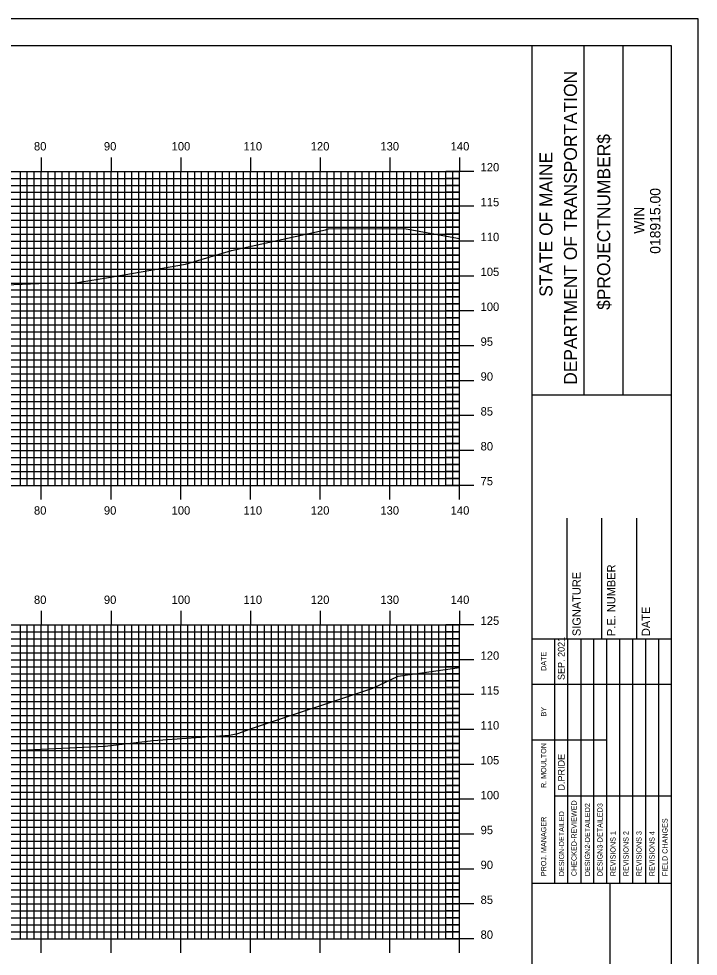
# Model space of a CAD drawing. Extents: x 1755495 to 1755838, y 442591 to 442811.
# Drawn here: x 1755737.3 to 1755834.8, y 442676.2 to 442810.5 of the extents above; entities that cross this region are included whole.
import ezdxf

# ---------------------------------------------------------------- set-up
doc = ezdxf.new("R2010")
doc.units = 0
for name, color, linetype in [('BORDER', 7, 'Continuous'), ('H_V ANNOTATION', 7, 'Continuous'), ('MAJOR', 7, 'Continuous'), ('MINOR', 7, 'Continuous'), ('PLOT BOUNDARY', 7, 'Continuous'), ('S_Roadway_Centerline', 7, 'Continuous')]:
    doc.layers.add(name, color=color, linetype=linetype)

msp = doc.modelspace()

# ---------------------------------------------------------------- linework, layer by layer
at = {"layer": 'BORDER'}
for p, q in [((1755810.94, 442596.67), (1755810.94, 442806.67)), ((1755818.4, 442756.66), (1755818.4, 442806.66)), ((1755823.99, 442756.66), (1755823.99, 442806.66)), ((1755810.95, 442756.65), (1755830.94, 442756.65)), ((1755815.94, 442721.67), (1755815.94, 442738.97)), ((1755820.94, 442721.67), (1755820.94, 442738.97)), ((1755825.94, 442721.67), (1755825.94, 442738.97)), ((1755810.94, 442721.67), (1755830.94, 442721.67)), ((1755810.94, 442686.67), (1755830.94, 442686.67)), ((1755822.13, 442616.67), (1755822.13, 442686.67))]:
    msp.add_line(p, q, dxfattribs=at)
msp.add_lwpolyline([(1755510.94, 442596.67), (1755830.94, 442596.67), (1755830.94, 442806.67), (1755510.94, 442806.67)], close=True, dxfattribs=at)
for points in [[(1755814.17, 442715.17), (1755814.17, 442721.67)], [(1755816.04, 442686.68), (1755816.04, 442721.67)], [(1755817.9, 442721.67), (1755817.9, 442686.68)], [(1755819.77, 442686.68), (1755819.77, 442721.67)], [(1755821.63, 442686.68), (1755821.63, 442721.67)], [(1755823.49, 442686.68), (1755823.49, 442721.67)], [(1755825.36, 442686.68), (1755825.36, 442721.67)], [(1755827.22, 442686.68), (1755827.22, 442721.67)], [(1755829.08, 442686.68), (1755829.08, 442721.67)], [(1755814.18, 442686.68), (1755814.18, 442720.26)], [(1755810.94, 442715.17), (1755830.94, 442715.17)], [(1755810.94, 442707.17), (1755814.18, 442707.17)], [(1755814.17, 442707.17), (1755821.63, 442707.17)], [(1755814.17, 442699.17), (1755830.94, 442699.17)]]:
    msp.add_lwpolyline(points, dxfattribs=at)
at = {"layer": 'MAJOR'}
for p, q in [((1755740.54, 442790.67), (1755740.54, 442788.67)), ((1755750.54, 442790.67), (1755750.54, 442788.67)), ((1755760.54, 442790.67), (1755760.54, 442788.67)), ((1755770.54, 442790.67), (1755770.54, 442788.67)), ((1755780.54, 442790.67), (1755780.54, 442788.67)), ((1755790.54, 442790.67), (1755790.54, 442788.67)), ((1755800.54, 442790.67), (1755800.54, 442788.67)), ((1755520.54, 442788.67), (1755800.54, 442788.67)), ((1755520.54, 442788.67), (1755800.54, 442788.67)), ((1755740.54, 442743.67), (1755740.54, 442788.67)), ((1755750.54, 442743.67), (1755750.54, 442788.67)), ((1755760.54, 442743.67), (1755760.54, 442788.67)), ((1755770.54, 442743.67), (1755770.54, 442788.67)), ((1755780.54, 442743.67), (1755780.54, 442788.67)), ((1755790.54, 442743.67), (1755790.54, 442788.67)), ((1755802.55, 442788.67), (1755798.54, 442788.67)), ((1755800.54, 442743.67), (1755800.54, 442788.67)), ((1755800.54, 442743.67), (1755800.54, 442788.67)), ((1755520.54, 442783.67), (1755800.54, 442783.67)), ((1755802.55, 442783.67), (1755798.54, 442783.67)), ((1755520.54, 442778.67), (1755800.54, 442778.67)), ((1755802.55, 442778.67), (1755798.54, 442778.67)), ((1755520.54, 442773.67), (1755800.54, 442773.67)), ((1755802.55, 442773.67), (1755798.54, 442773.67)), ((1755520.54, 442768.67), (1755800.54, 442768.67)), ((1755802.55, 442768.67), (1755798.54, 442768.67)), ((1755520.54, 442763.67), (1755800.54, 442763.67)), ((1755802.55, 442763.67), (1755798.54, 442763.67)), ((1755520.54, 442758.67), (1755800.54, 442758.67)), ((1755802.55, 442758.67), (1755798.54, 442758.67)), ((1755520.54, 442753.67), (1755800.54, 442753.67)), ((1755802.55, 442753.67), (1755798.54, 442753.67)), ((1755520.54, 442748.67), (1755800.54, 442748.67)), ((1755802.55, 442748.67), (1755798.54, 442748.67)), ((1755520.54, 442743.67), (1755800.54, 442743.67)), ((1755520.54, 442743.67), (1755800.54, 442743.67)), ((1755740.54, 442741.66), (1755740.54, 442743.67)), ((1755750.54, 442741.66), (1755750.54, 442743.67)), ((1755760.54, 442741.66), (1755760.54, 442743.67)), ((1755770.54, 442741.66), (1755770.54, 442743.67)), ((1755780.54, 442741.66), (1755780.54, 442743.67)), ((1755790.54, 442741.66), (1755790.54, 442743.67)), ((1755802.55, 442743.67), (1755798.54, 442743.67)), ((1755800.54, 442741.66), (1755800.54, 442743.67)), ((1755740.54, 442725.67), (1755740.54, 442723.67)), ((1755750.54, 442725.67), (1755750.54, 442723.67)), ((1755760.54, 442725.67), (1755760.54, 442723.67)), ((1755770.54, 442725.67), (1755770.54, 442723.67)), ((1755780.54, 442725.67), (1755780.54, 442723.67)), ((1755790.54, 442725.67), (1755790.54, 442723.67)), ((1755800.54, 442725.67), (1755800.54, 442723.67)), ((1755520.54, 442723.67), (1755800.54, 442723.67)), ((1755520.54, 442723.67), (1755800.54, 442723.67)), ((1755740.54, 442678.67), (1755740.54, 442723.67)), ((1755750.54, 442678.67), (1755750.54, 442723.67)), ((1755760.54, 442678.67), (1755760.54, 442723.67)), ((1755770.54, 442678.67), (1755770.54, 442723.67)), ((1755780.54, 442678.67), (1755780.54, 442723.67)), ((1755790.54, 442678.67), (1755790.54, 442723.67)), ((1755802.55, 442723.67), (1755798.54, 442723.67)), ((1755800.54, 442678.67), (1755800.54, 442723.67)), ((1755800.54, 442678.67), (1755800.54, 442723.67)), ((1755520.54, 442718.67), (1755800.54, 442718.67)), ((1755802.55, 442718.67), (1755798.54, 442718.67)), ((1755520.54, 442713.67), (1755800.54, 442713.67)), ((1755802.55, 442713.67), (1755798.54, 442713.67)), ((1755520.54, 442708.67), (1755800.54, 442708.67)), ((1755802.55, 442708.67), (1755798.54, 442708.67)), ((1755520.54, 442703.67), (1755800.54, 442703.67)), ((1755802.55, 442703.67), (1755798.54, 442703.67)), ((1755520.54, 442698.67), (1755800.54, 442698.67)), ((1755802.55, 442698.67), (1755798.54, 442698.67)), ((1755520.54, 442693.67), (1755800.54, 442693.67)), ((1755802.55, 442693.67), (1755798.54, 442693.67)), ((1755520.54, 442688.67), (1755800.54, 442688.67)), ((1755802.55, 442688.67), (1755798.54, 442688.67)), ((1755520.54, 442683.67), (1755800.54, 442683.67)), ((1755802.55, 442683.67), (1755798.54, 442683.67)), ((1755520.54, 442678.67), (1755800.54, 442678.67)), ((1755520.54, 442678.67), (1755800.54, 442678.67)), ((1755740.54, 442676.66), (1755740.54, 442678.67)), ((1755750.54, 442676.66), (1755750.54, 442678.67)), ((1755760.54, 442676.66), (1755760.54, 442678.67)), ((1755770.54, 442676.66), (1755770.54, 442678.67)), ((1755780.54, 442676.66), (1755780.54, 442678.67)), ((1755790.54, 442676.66), (1755790.54, 442678.67)), ((1755802.55, 442678.67), (1755798.54, 442678.67)), ((1755800.54, 442676.66), (1755800.54, 442678.67))]:
    msp.add_line(p, q, dxfattribs=at)
at = {"layer": 'MINOR'}
for p, q in [((1755737.54, 442743.67), (1755737.54, 442788.67)), ((1755738.54, 442743.67), (1755738.54, 442788.67)), ((1755739.54, 442743.67), (1755739.54, 442788.67)), ((1755741.54, 442743.67), (1755741.54, 442788.67)), ((1755742.54, 442743.67), (1755742.54, 442788.67)), ((1755743.54, 442743.67), (1755743.54, 442788.67)), ((1755744.54, 442743.67), (1755744.54, 442788.67)), ((1755745.54, 442743.67), (1755745.54, 442788.67)), ((1755746.54, 442743.67), (1755746.54, 442788.67)), ((1755747.54, 442743.67), (1755747.54, 442788.67)), ((1755748.54, 442743.67), (1755748.54, 442788.67)), ((1755749.54, 442743.67), (1755749.54, 442788.67)), ((1755751.54, 442743.67), (1755751.54, 442788.67)), ((1755752.54, 442743.67), (1755752.54, 442788.67)), ((1755753.54, 442743.67), (1755753.54, 442788.67)), ((1755754.54, 442743.67), (1755754.54, 442788.67)), ((1755755.54, 442743.67), (1755755.54, 442788.67)), ((1755756.54, 442743.67), (1755756.54, 442788.67)), ((1755757.54, 442743.67), (1755757.54, 442788.67)), ((1755758.54, 442743.67), (1755758.54, 442788.67)), ((1755759.54, 442743.67), (1755759.54, 442788.67)), ((1755761.54, 442743.67), (1755761.54, 442788.67)), ((1755762.54, 442743.67), (1755762.54, 442788.67)), ((1755763.54, 442743.67), (1755763.54, 442788.67)), ((1755764.54, 442743.67), (1755764.54, 442788.67)), ((1755765.54, 442743.67), (1755765.54, 442788.67)), ((1755766.54, 442743.67), (1755766.54, 442788.67)), ((1755767.54, 442743.67), (1755767.54, 442788.67)), ((1755768.54, 442743.67), (1755768.54, 442788.67)), ((1755769.54, 442743.67), (1755769.54, 442788.67)), ((1755771.54, 442743.67), (1755771.54, 442788.67)), ((1755772.54, 442743.67), (1755772.54, 442788.67)), ((1755773.54, 442743.67), (1755773.54, 442788.67)), ((1755774.54, 442743.67), (1755774.54, 442788.67)), ((1755775.54, 442743.67), (1755775.54, 442788.67)), ((1755776.54, 442743.67), (1755776.54, 442788.67)), ((1755777.54, 442743.67), (1755777.54, 442788.67)), ((1755778.54, 442743.67), (1755778.54, 442788.67)), ((1755779.54, 442743.67), (1755779.54, 442788.67)), ((1755781.54, 442743.67), (1755781.54, 442788.67)), ((1755782.54, 442743.67), (1755782.54, 442788.67)), ((1755783.54, 442743.67), (1755783.54, 442788.67)), ((1755784.54, 442743.67), (1755784.54, 442788.67)), ((1755785.54, 442743.67), (1755785.54, 442788.67)), ((1755786.54, 442743.67), (1755786.54, 442788.67)), ((1755787.54, 442743.67), (1755787.54, 442788.67)), ((1755788.54, 442743.67), (1755788.54, 442788.67)), ((1755789.54, 442743.67), (1755789.54, 442788.67)), ((1755791.54, 442743.67), (1755791.54, 442788.67)), ((1755792.54, 442743.67), (1755792.54, 442788.67)), ((1755793.54, 442743.67), (1755793.54, 442788.67)), ((1755794.54, 442743.67), (1755794.54, 442788.67)), ((1755795.54, 442743.67), (1755795.54, 442788.67)), ((1755796.54, 442743.67), (1755796.54, 442788.67)), ((1755797.54, 442743.67), (1755797.54, 442788.67)), ((1755798.54, 442743.67), (1755798.54, 442788.67)), ((1755799.54, 442743.67), (1755799.54, 442788.67)), ((1755520.54, 442787.67), (1755800.54, 442787.67)), ((1755520.54, 442786.67), (1755800.54, 442786.67)), ((1755800.54, 442787.67), (1755798.54, 442787.67)), ((1755800.54, 442786.67), (1755798.54, 442786.67)), ((1755520.54, 442785.67), (1755800.54, 442785.67)), ((1755800.54, 442785.67), (1755798.54, 442785.67)), ((1755520.54, 442784.67), (1755800.54, 442784.67)), ((1755800.54, 442784.67), (1755798.54, 442784.67)), ((1755520.54, 442782.67), (1755800.54, 442782.67)), ((1755800.54, 442782.67), (1755798.54, 442782.67)), ((1755520.54, 442781.67), (1755800.54, 442781.67)), ((1755800.54, 442781.67), (1755798.54, 442781.67)), ((1755520.54, 442780.67), (1755800.54, 442780.67)), ((1755520.54, 442779.67), (1755800.54, 442779.67)), ((1755800.54, 442780.67), (1755798.54, 442780.67)), ((1755800.54, 442779.67), (1755798.54, 442779.67)), ((1755520.54, 442777.67), (1755800.54, 442777.67)), ((1755800.54, 442777.67), (1755798.54, 442777.67)), ((1755520.54, 442776.67), (1755800.54, 442776.67)), ((1755520.54, 442775.67), (1755800.54, 442775.67)), ((1755800.54, 442776.67), (1755798.54, 442776.67)), ((1755800.54, 442775.67), (1755798.54, 442775.67)), ((1755520.54, 442774.67), (1755800.54, 442774.67)), ((1755800.54, 442774.67), (1755798.54, 442774.67)), ((1755520.54, 442772.67), (1755800.54, 442772.67)), ((1755520.54, 442771.67), (1755800.54, 442771.67)), ((1755800.54, 442772.67), (1755798.54, 442772.67)), ((1755800.54, 442771.67), (1755798.54, 442771.67)), ((1755520.54, 442770.67), (1755800.54, 442770.67)), ((1755800.54, 442770.67), (1755798.54, 442770.67)), ((1755520.54, 442769.67), (1755800.54, 442769.67)), ((1755800.54, 442769.67), (1755798.54, 442769.67)), ((1755520.54, 442767.67), (1755800.54, 442767.67)), ((1755800.54, 442767.67), (1755798.54, 442767.67)), ((1755520.54, 442766.67), (1755800.54, 442766.67)), ((1755800.54, 442766.67), (1755798.54, 442766.67)), ((1755520.54, 442765.67), (1755800.54, 442765.67)), ((1755800.54, 442765.67), (1755798.54, 442765.67)), ((1755520.54, 442764.67), (1755800.54, 442764.67)), ((1755800.54, 442764.67), (1755798.54, 442764.67)), ((1755520.54, 442762.67), (1755800.54, 442762.67)), ((1755800.54, 442762.67), (1755798.54, 442762.67)), ((1755520.54, 442761.67), (1755800.54, 442761.67)), ((1755800.54, 442761.67), (1755798.54, 442761.67)), ((1755520.54, 442760.67), (1755800.54, 442760.67)), ((1755520.54, 442759.67), (1755800.54, 442759.67)), ((1755800.54, 442760.67), (1755798.54, 442760.67)), ((1755800.54, 442759.67), (1755798.54, 442759.67)), ((1755520.54, 442757.67), (1755800.54, 442757.67)), ((1755800.54, 442757.67), (1755798.54, 442757.67)), ((1755520.54, 442756.67), (1755800.54, 442756.67)), ((1755520.54, 442755.67), (1755800.54, 442755.67)), ((1755800.54, 442756.67), (1755798.54, 442756.67)), ((1755800.54, 442755.67), (1755798.54, 442755.67)), ((1755520.54, 442754.67), (1755800.54, 442754.67)), ((1755800.54, 442754.67), (1755798.54, 442754.67)), ((1755520.54, 442752.67), (1755800.54, 442752.67)), ((1755520.54, 442751.67), (1755800.54, 442751.67)), ((1755800.54, 442752.67), (1755798.54, 442752.67)), ((1755800.54, 442751.67), (1755798.54, 442751.67)), ((1755520.54, 442750.67), (1755800.54, 442750.67)), ((1755800.54, 442750.67), (1755798.54, 442750.67)), ((1755520.54, 442749.67), (1755800.54, 442749.67)), ((1755800.54, 442749.67), (1755798.54, 442749.67)), ((1755520.54, 442747.67), (1755800.54, 442747.67)), ((1755800.54, 442747.67), (1755798.54, 442747.67)), ((1755520.54, 442746.67), (1755800.54, 442746.67)), ((1755800.54, 442746.67), (1755798.54, 442746.67)), ((1755520.54, 442745.67), (1755800.54, 442745.67)), ((1755800.54, 442745.67), (1755798.54, 442745.67)), ((1755520.54, 442744.67), (1755800.54, 442744.67)), ((1755800.54, 442744.67), (1755798.54, 442744.67)), ((1755737.54, 442678.67), (1755737.54, 442723.67)), ((1755738.54, 442678.67), (1755738.54, 442723.67)), ((1755739.54, 442678.67), (1755739.54, 442723.67)), ((1755741.54, 442678.67), (1755741.54, 442723.67)), ((1755742.54, 442678.67), (1755742.54, 442723.67)), ((1755743.54, 442678.67), (1755743.54, 442723.67)), ((1755744.54, 442678.67), (1755744.54, 442723.67)), ((1755745.54, 442678.67), (1755745.54, 442723.67)), ((1755746.54, 442678.67), (1755746.54, 442723.67)), ((1755747.54, 442678.67), (1755747.54, 442723.67)), ((1755748.54, 442678.67), (1755748.54, 442723.67)), ((1755749.54, 442678.67), (1755749.54, 442723.67)), ((1755751.54, 442678.67), (1755751.54, 442723.67)), ((1755752.54, 442678.67), (1755752.54, 442723.67)), ((1755753.54, 442678.67), (1755753.54, 442723.67)), ((1755754.54, 442678.67), (1755754.54, 442723.67)), ((1755755.54, 442678.67), (1755755.54, 442723.67)), ((1755756.54, 442678.67), (1755756.54, 442723.67)), ((1755757.54, 442678.67), (1755757.54, 442723.67)), ((1755758.54, 442678.67), (1755758.54, 442723.67)), ((1755759.54, 442678.67), (1755759.54, 442723.67)), ((1755761.54, 442678.67), (1755761.54, 442723.67)), ((1755762.54, 442678.67), (1755762.54, 442723.67)), ((1755763.54, 442678.67), (1755763.54, 442723.67)), ((1755764.54, 442678.67), (1755764.54, 442723.67)), ((1755765.54, 442678.67), (1755765.54, 442723.67)), ((1755766.54, 442678.67), (1755766.54, 442723.67)), ((1755767.54, 442678.67), (1755767.54, 442723.67)), ((1755768.54, 442678.67), (1755768.54, 442723.67)), ((1755769.54, 442678.67), (1755769.54, 442723.67)), ((1755771.54, 442678.67), (1755771.54, 442723.67)), ((1755772.54, 442678.67), (1755772.54, 442723.67)), ((1755773.54, 442678.67), (1755773.54, 442723.67)), ((1755774.54, 442678.67), (1755774.54, 442723.67)), ((1755775.54, 442678.67), (1755775.54, 442723.67)), ((1755776.54, 442678.67), (1755776.54, 442723.67)), ((1755777.54, 442678.67), (1755777.54, 442723.67)), ((1755778.54, 442678.67), (1755778.54, 442723.67)), ((1755779.54, 442678.67), (1755779.54, 442723.67)), ((1755781.54, 442678.67), (1755781.54, 442723.67)), ((1755782.54, 442678.67), (1755782.54, 442723.67)), ((1755783.54, 442678.67), (1755783.54, 442723.67)), ((1755784.54, 442678.67), (1755784.54, 442723.67)), ((1755785.54, 442678.67), (1755785.54, 442723.67)), ((1755786.54, 442678.67), (1755786.54, 442723.67)), ((1755787.54, 442678.67), (1755787.54, 442723.67)), ((1755788.54, 442678.67), (1755788.54, 442723.67)), ((1755789.54, 442678.67), (1755789.54, 442723.67)), ((1755791.54, 442678.67), (1755791.54, 442723.67)), ((1755792.54, 442678.67), (1755792.54, 442723.67)), ((1755793.54, 442678.67), (1755793.54, 442723.67)), ((1755794.54, 442678.67), (1755794.54, 442723.67)), ((1755795.54, 442678.67), (1755795.54, 442723.67)), ((1755796.54, 442678.67), (1755796.54, 442723.67)), ((1755797.54, 442678.67), (1755797.54, 442723.67)), ((1755798.54, 442678.67), (1755798.54, 442723.67)), ((1755799.54, 442678.67), (1755799.54, 442723.67)), ((1755520.54, 442722.67), (1755800.54, 442722.67)), ((1755800.54, 442722.67), (1755798.54, 442722.67)), ((1755520.54, 442721.67), (1755800.54, 442721.67)), ((1755520.54, 442720.67), (1755800.54, 442720.67)), ((1755800.54, 442721.67), (1755798.54, 442721.67)), ((1755800.54, 442720.67), (1755798.54, 442720.67)), ((1755520.54, 442719.67), (1755800.54, 442719.67)), ((1755800.54, 442719.67), (1755798.54, 442719.67)), ((1755520.54, 442717.67), (1755800.54, 442717.67)), ((1755520.54, 442716.67), (1755800.54, 442716.67)), ((1755800.54, 442717.67), (1755798.54, 442717.67)), ((1755800.54, 442716.67), (1755798.54, 442716.67)), ((1755520.54, 442715.67), (1755800.54, 442715.67)), ((1755800.54, 442715.67), (1755798.54, 442715.67)), ((1755520.54, 442714.67), (1755800.54, 442714.67)), ((1755800.54, 442714.67), (1755798.54, 442714.67)), ((1755520.54, 442712.67), (1755800.54, 442712.67)), ((1755800.54, 442712.67), (1755798.54, 442712.67)), ((1755520.54, 442711.67), (1755800.54, 442711.67)), ((1755800.54, 442711.67), (1755798.54, 442711.67)), ((1755520.54, 442710.67), (1755800.54, 442710.67)), ((1755800.54, 442710.67), (1755798.54, 442710.67)), ((1755520.54, 442709.67), (1755800.54, 442709.67)), ((1755800.54, 442709.67), (1755798.54, 442709.67)), ((1755520.54, 442707.67), (1755800.54, 442707.67)), ((1755800.54, 442707.67), (1755798.54, 442707.67)), ((1755520.54, 442706.67), (1755800.54, 442706.67)), ((1755800.54, 442706.67), (1755798.54, 442706.67)), ((1755520.54, 442705.67), (1755800.54, 442705.67)), ((1755520.54, 442704.67), (1755800.54, 442704.67)), ((1755800.54, 442705.67), (1755798.54, 442705.67)), ((1755800.54, 442704.67), (1755798.54, 442704.67)), ((1755520.54, 442702.67), (1755800.54, 442702.67)), ((1755800.54, 442702.67), (1755798.54, 442702.67)), ((1755520.54, 442701.67), (1755800.54, 442701.67)), ((1755520.54, 442700.67), (1755800.54, 442700.67)), ((1755800.54, 442701.67), (1755798.54, 442701.67)), ((1755800.54, 442700.67), (1755798.54, 442700.67)), ((1755520.54, 442699.67), (1755800.54, 442699.67)), ((1755800.54, 442699.67), (1755798.54, 442699.67)), ((1755520.54, 442697.67), (1755800.54, 442697.67)), ((1755520.54, 442696.67), (1755800.54, 442696.67)), ((1755800.54, 442697.67), (1755798.54, 442697.67)), ((1755800.54, 442696.67), (1755798.54, 442696.67)), ((1755520.54, 442695.67), (1755800.54, 442695.67)), ((1755800.54, 442695.67), (1755798.54, 442695.67)), ((1755520.54, 442694.67), (1755800.54, 442694.67)), ((1755800.54, 442694.67), (1755798.54, 442694.67)), ((1755520.54, 442692.67), (1755800.54, 442692.67)), ((1755800.54, 442692.67), (1755798.54, 442692.67)), ((1755520.54, 442691.67), (1755800.54, 442691.67)), ((1755800.54, 442691.67), (1755798.54, 442691.67)), ((1755520.54, 442690.67), (1755800.54, 442690.67)), ((1755520.54, 442689.67), (1755800.54, 442689.67)), ((1755800.54, 442690.67), (1755798.54, 442690.67)), ((1755800.54, 442689.67), (1755798.54, 442689.67)), ((1755520.54, 442687.67), (1755800.54, 442687.67)), ((1755800.54, 442687.67), (1755798.54, 442687.67)), ((1755520.54, 442686.67), (1755800.54, 442686.67)), ((1755520.54, 442685.67), (1755800.54, 442685.67)), ((1755800.54, 442686.67), (1755798.54, 442686.67)), ((1755800.54, 442685.67), (1755798.54, 442685.67)), ((1755520.54, 442684.67), (1755800.54, 442684.67)), ((1755800.54, 442684.67), (1755798.54, 442684.67)), ((1755520.54, 442682.67), (1755800.54, 442682.67)), ((1755520.54, 442681.67), (1755800.54, 442681.67)), ((1755800.54, 442682.67), (1755798.54, 442682.67)), ((1755800.54, 442681.67), (1755798.54, 442681.67)), ((1755520.54, 442680.67), (1755800.54, 442680.67)), ((1755800.54, 442680.67), (1755798.54, 442680.67)), ((1755520.54, 442679.67), (1755800.54, 442679.67)), ((1755800.54, 442679.67), (1755798.54, 442679.67))]:
    msp.add_line(p, q, dxfattribs=at)
at = {"layer": 'PLOT BOUNDARY'}
msp.add_lwpolyline([(1755494.76, 442590.55), (1755834.76, 442590.55), (1755834.76, 442810.55), (1755494.76, 442810.55)], close=True, dxfattribs=at)
at = {"layer": 'S_Roadway_Centerline'}
for points in [[(1755729.34, 442772.17), (1755742.58, 442772.68), (1755745.12, 442772.67), (1755749.87, 442773.41), (1755761.22, 442775.39), (1755767.82, 442777.35), (1755781.29, 442780.28), (1755781.74, 442780.44), (1755782.5, 442780.49), (1755792.88, 442780.44), (1755800.54, 442779.06)], [(1755731.09, 442705.41), (1755737.51, 442705.7), (1755749.69, 442706.3), (1755756.58, 442707.08), (1755767.52, 442707.86), (1755768.74, 442708.08), (1755770.96, 442708.91), (1755788.11, 442714.61), (1755791.71, 442716.32), (1755800.54, 442717.54)]]:
    msp.add_lwpolyline(points, dxfattribs=at)

# ---------------------------------------------------------------- texts
at = {"layer": 'BORDER'}
for s, height, p in [('DEPARTMENT OF TRANSPORTATION', 1.8635, (1755817.36, 442758.08)), ('$PROJECTNUMBER$', 1.8635, (1755822.13, 442768.82)), ('STATE OF MAINE', 1.8635, (1755813.85, 442770.69)), ('018915.00', 1.491, (1755829.33, 442776.86)), ('WIN', 1.491, (1755827.02, 442779.73)), ('P.E. NUMBER', 1.1811, (1755822.87, 442722.06)), ('SIGNATURE', 1.181, (1755817.9, 442722.06)), ('DATE', 1.181, (1755827.83, 442722.06)), ('SEP. 2021', 0.969, (1755815.59, 442715.76)), ('DATE', 0.743, (1755812.95, 442717.08)), ('BY', 0.743, (1755812.95, 442710.54)), ('R. MOULTON', 0.745, (1755812.95, 442700.28)), ('D.PRIDE', 0.969, (1755815.59, 442699.92)), ('D.PRIDE', 0.969, (1755815.59, 442699.92)), ('CHECKED-REVIEWED', 0.7455, (1755817.31, 442687.65)), ('DESIGN2-DETAILED2', 0.7455, (1755819.24, 442687.65)), ('DESIGN3-DETAILED3', 0.7455, (1755821.03, 442687.65)), ('DESIGN-DETAILED', 0.7455, (1755815.52, 442687.65)), ('PROJ. MANAGER', 0.7455, (1755812.95, 442687.65)), ('FIELD CHANGES', 0.7455, (1755830.35, 442687.65)), ('REVISIONS 1', 0.7455, (1755822.9, 442687.65)), ('REVISIONS 2', 0.7455, (1755824.76, 442687.65)), ('REVISIONS 3', 0.7455, (1755826.62, 442687.65)), ('REVISIONS 4', 0.7455, (1755828.49, 442687.65))]:
    msp.add_text(s, height=height, rotation=90, dxfattribs=at).set_placement(p)
at = {"layer": 'H_V ANNOTATION'}
for s, p in [('80', (1755739.49, 442791.67)), ('90', (1755749.52, 442791.67)), ('100', (1755759.23, 442791.67)), ('110', (1755769.53, 442791.67)), ('120', (1755779.18, 442791.67)), ('130', (1755789.17, 442791.67)), ('140', (1755799.25, 442791.67)), ('120', (1755803.54, 442788.67)), ('115', (1755803.54, 442783.67)), ('110', (1755803.54, 442778.67)), ('105', (1755803.54, 442773.67)), ('100', (1755803.54, 442768.67)), ('95', (1755803.54, 442763.67)), ('90', (1755803.54, 442758.67)), ('85', (1755803.54, 442753.67)), ('80', (1755803.54, 442748.67)), ('75', (1755803.54, 442743.67)), ('80', (1755739.49, 442739.47)), ('90', (1755749.52, 442739.47)), ('100', (1755759.23, 442739.47)), ('110', (1755769.53, 442739.47)), ('120', (1755779.18, 442739.47)), ('130', (1755789.17, 442739.47)), ('140', (1755799.25, 442739.47)), ('80', (1755739.49, 442726.67)), ('90', (1755749.52, 442726.67)), ('100', (1755759.23, 442726.67)), ('110', (1755769.53, 442726.67)), ('120', (1755779.18, 442726.67)), ('130', (1755789.17, 442726.67)), ('140', (1755799.25, 442726.67)), ('125', (1755803.54, 442723.67)), ('120', (1755803.54, 442718.67)), ('115', (1755803.54, 442713.67)), ('110', (1755803.54, 442708.67)), ('105', (1755803.54, 442703.67)), ('100', (1755803.54, 442698.67)), ('95', (1755803.54, 442693.67)), ('90', (1755803.54, 442688.67)), ('85', (1755803.54, 442683.67)), ('80', (1755803.54, 442678.67))]:
    msp.add_text(s, height=1.2, dxfattribs=at).set_placement(p)

doc.saveas('drawing.dxf')
